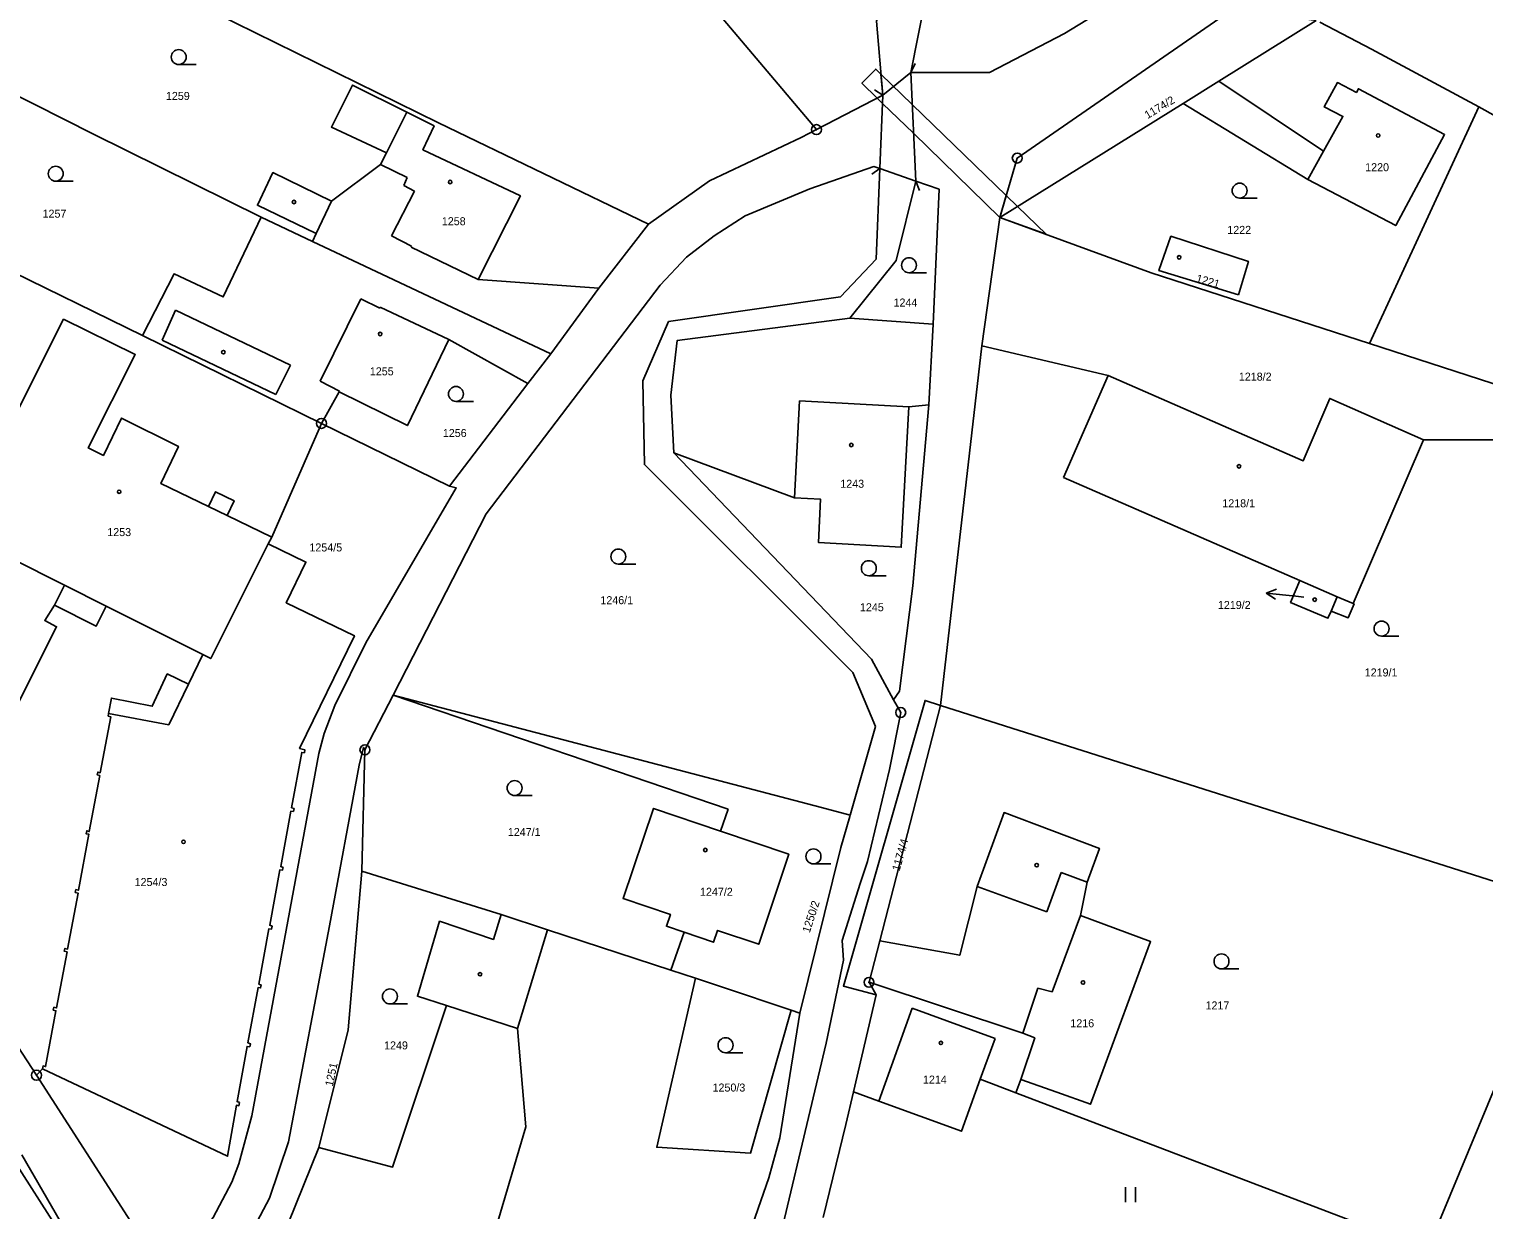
# Model space of a CAD drawing. Extents: x -587171 to -555306, y -1167727 to -1074732.
# Drawn here: x -559980.4 to -559834.5, y -1076843.9 to -1076725.4 of the extents above; entities that cross this region are included whole.
import ezdxf

# ---------------------------------------------------------------- set-up
doc = ezdxf.new("R2010")
doc.units = 0
for name, color, linetype in [('Hranice parcel', 7, 'Continuous'), ('Parcelní čísla', 7, 'Continuous'), ('Pop  PČ popisy', 7, 'Continuous'), ('Poz předměty', 7, 'Continuous'), ('Vnitřní kresba', 7, 'Continuous'), ('Věcná břemena k části', 7, 'Continuous'), ('Značky bodu BP', 7, 'Continuous'), ('Značky budov', 7, 'Continuous'), ('Značky kultur', 7, 'Continuous')]:
    doc.layers.add(name, color=color, linetype=linetype)

msp = doc.modelspace()

# ---------------------------------------------------------------- linework, layer by layer
at = {"layer": 'Hranice parcel'}
for p, q in [((-559861.1, -1076730.63), (-559851.34, -1076724.55)), ((-559892, -1076729.76), (-559891.5, -1076740.66)), ((-559864.67, -1076732.85), (-559861.1, -1076730.63)), ((-559894.79, -1076732.04), (-559901.45, -1076735.49)), ((-559895.09, -1076739.4), (-559894.79, -1076732.04)), ((-559883.05, -1076744.29), (-559864.67, -1076732.85)), ((-559845.98, -1076756.95), (-559835.03, -1076733.2)), ((-559828.11, -1076737.08), (-559835.03, -1076733.2)), ((-560001.56, -1076740.2), (-559969.04, -1076756.15)), ((-559889.14, -1076741.46), (-559891.5, -1076740.66)), ((-559889.75, -1076754.99), (-559889.14, -1076741.46)), ((-559951.99, -1076746.71), (-559957.13, -1076744.28)), ((-559918.29, -1076744.98), (-559923.28, -1076751.41)), ((-559883.05, -1076744.29), (-559884.86, -1076757.19)), ((-559928.09, -1076757.97), (-559951.99, -1076746.71)), ((-559923.28, -1076751.41), (-559928.09, -1076757.97)), ((-559889.75, -1076754.99), (-559898.09, -1076754.41)), ((-559890.17, -1076763.1), (-559889.75, -1076754.99)), ((-559969.04, -1076756.15), (-559951.09, -1076764.96)), ((-559830.5, -1076761.96), (-559845.98, -1076756.95)), ((-559928.09, -1076757.97), (-559930.38, -1076760.96)), ((-559884.86, -1076757.19), (-559889.01, -1076793.25)), ((-559884.86, -1076757.19), (-559872.19, -1076760.16)), ((-559930.38, -1076760.96), (-559938.25, -1076771.25)), ((-559872.19, -1076760.16), (-559876.67, -1076770.39)), ((-559956.07, -1076776.37), (-559951.09, -1076764.96)), ((-559951.09, -1076764.96), (-559938.25, -1076771.25)), ((-559847.63, -1076783.04), (-559840.58, -1076766.61)), ((-559840.58, -1076766.61), (-559823.35, -1076766.61)), ((-559876.67, -1076770.39), (-559852.96, -1076780.72)), ((-559956.42, -1076777.06), (-559956.07, -1076776.37)), ((-559943.91, -1076792.23), (-559946.73, -1076797.71)), ((-559910.3, -1076803.67), (-559943.91, -1076792.23)), ((-559889.01, -1076793.25), (-559895.1, -1076816.87)), ((-559825.87, -1076813.36), (-559889.01, -1076793.25)), ((-559946.73, -1076797.71), (-559947.03, -1076809.88)), ((-559911.09, -1076805.87), (-559910.3, -1076803.67)), ((-559947.03, -1076809.88), (-559933.08, -1076814.22)), ((-559840.17, -1076847.86), (-559825.87, -1076813.36)), ((-559933.08, -1076814.22), (-559928.42, -1076815.77)), ((-559928.42, -1076815.77), (-559916.07, -1076819.81)), ((-559916.07, -1076819.81), (-559914.72, -1076816.02)), ((-559895.1, -1076816.87), (-559896.18, -1076821.04)), ((-559916.07, -1076819.81), (-559913.57, -1076820.63)), ((-559896.18, -1076821.04), (-559895.46, -1076822.31)), ((-559895.46, -1076822.31), (-559897.72, -1076832.03)), ((-559903.99, -1076823.85), (-559903.12, -1076824.14)), ((-559979.67, -1076830.36), (-559979.07, -1076829.73)), ((-559881.44, -1076832.12), (-559880.97, -1076830.78)), ((-559840.17, -1076847.86), (-559881.44, -1076832.12)), ((-559951.35, -1076837.61), (-559960.01, -1076858.96))]:
    msp.add_line(p, q, dxfattribs=at)
for points in [[(-559958.09, -1076699.95), (-559954.36, -1076701.7), (-559913.91, -1076720.68), (-559901.45, -1076735.49)], [(-559894.79, -1076732.04), (-559895.44, -1076724.62), (-559892.05, -1076713.34), (-559886.72, -1076702.24)], [(-559885.03, -1076703.32), (-559887.56, -1076708.1), (-559889.85, -1076718.91), (-559892, -1076729.76)], [(-559892, -1076729.76), (-559884.1, -1076729.75), (-559876.58, -1076725.85), (-559869.98, -1076721.78), (-559855.77, -1076713.57), (-559855.15, -1076713.16)], [(-559918.29, -1076744.98), (-559939.37, -1076734.8), (-559961.79, -1076723.77), (-559967.51, -1076721.16)], [(-559851.34, -1076724.55), (-559859.71, -1076723.41), (-559881.31, -1076738.34), (-559883.05, -1076744.29)], [(-559835.03, -1076733.2), (-559845.8, -1076727.41), (-559850.96, -1076724.72)], [(-559957.13, -1076744.28), (-559973.96, -1076735.95), (-559994.8, -1076725.4)], [(-559864.67, -1076732.85), (-559852.18, -1076740.5), (-559843.36, -1076745.12), (-559838.45, -1076735.98), (-559847.1, -1076731.38), (-559847.3, -1076731.75), (-559849.21, -1076730.76), (-559850.53, -1076733.21), (-559848.65, -1076734.16), (-559850.6, -1076737.65), (-559861.1, -1076730.63)], [(-559923.28, -1076751.41), (-559935.36, -1076750.52), (-559931.14, -1076742.14), (-559940.92, -1076737.5), (-559939.79, -1076735.11), (-559942.52, -1076733.74), (-559947.97, -1076731.02), (-559950.09, -1076735.23), (-559944.57, -1076737.81), (-559945.16, -1076738.99), (-559950.08, -1076742.66), (-559955.96, -1076739.8), (-559957.51, -1076743.07), (-559951.62, -1076745.91), (-559951.99, -1076746.71)], [(-559901.45, -1076735.49), (-559902.97, -1076736.28), (-559912.17, -1076740.63), (-559918.29, -1076744.98)], [(-559895.09, -1076739.4), (-559895.7, -1076739.19), (-559902.1, -1076741.42), (-559908.6, -1076744.13), (-559911.72, -1076746.15), (-559914.48, -1076748.29), (-559917.14, -1076751.1), (-559934.56, -1076774.04), (-559943.91, -1076792.23)], [(-559898.06, -1076804.27), (-559895.52, -1076795.36), (-559897.79, -1076789.94), (-559918.71, -1076769.1), (-559918.87, -1076760.68), (-559916.28, -1076754.75), (-559899.04, -1076752.26), (-559895.45, -1076748.47), (-559895.09, -1076739.4)], [(-559891.5, -1076740.66), (-559893.46, -1076748.63), (-559898.09, -1076754.41)], [(-559957.13, -1076744.28), (-559960.94, -1076752.28), (-559965.87, -1076749.97), (-559969.04, -1076756.15)], [(-559845.98, -1076756.95), (-559867.87, -1076749.84), (-559883.05, -1076744.29)], [(-559859.11, -1076752.05), (-559858.13, -1076748.71), (-559865.9, -1076746.19), (-559867.1, -1076749.63), (-559859.11, -1076752.05)], [(-559956.07, -1076776.37), (-559960.56, -1076774.2), (-559959.85, -1076772.72), (-559961.71, -1076771.82), (-559962.42, -1076773.3), (-559967.2, -1076771), (-559965.43, -1076767.28), (-559971.14, -1076764.43), (-559972.96, -1076768.17), (-559974.48, -1076767.42), (-559969.76, -1076758.06), (-559976.96, -1076754.51), (-559987.65, -1076775.79), (-559976.87, -1076781.2), (-559977.88, -1076783.21)], [(-559898.09, -1076754.41), (-559915.43, -1076756.66), (-559916.07, -1076762.12), (-559915.74, -1076767.92)], [(-559951.09, -1076764.96), (-559949.31, -1076761.81), (-559942.47, -1076765.18), (-559938.33, -1076756.54), (-559930.38, -1076760.96)], [(-559840.58, -1076766.61), (-559849.97, -1076762.45), (-559852.63, -1076768.71), (-559872.19, -1076760.16)], [(-559915.74, -1076767.92), (-559903.66, -1076772.42), (-559901.05, -1076772.56), (-559901.25, -1076776.91), (-559892.95, -1076777.39), (-559892.18, -1076763.31), (-559890.17, -1076763.1)], [(-559893.71, -1076792.69), (-559893.13, -1076791.83), (-559891.78, -1076781.27), (-559890.17, -1076763.1)], [(-559915.74, -1076767.92), (-559895.94, -1076788.62), (-559893.71, -1076792.69)], [(-559938.25, -1076771.25), (-559937.57, -1076771.44), (-559946.65, -1076786.97), (-559949.75, -1076793.25), (-559950.81, -1076796.07), (-559951.35, -1076798.09), (-559958.07, -1076834.44), (-559959.38, -1076839.26), (-559960.09, -1076841.08), (-559961.95, -1076844.64), (-559962.87, -1076845.81), (-559964.08, -1076846.68), (-559965.52, -1076847.13), (-559967.49, -1076847.03), (-559968.86, -1076846.47), (-559969.95, -1076845.48), (-559979.67, -1076830.36)], [(-559979.07, -1076829.73), (-559960.51, -1076838.49), (-559959.62, -1076833.37), (-559959.37, -1076833.42), (-559959.32, -1076833.11), (-559959.55, -1076833.01), (-559958.55, -1076827.47), (-559958.29, -1076827.5), (-559958.22, -1076827.21), (-559958.46, -1076827.11), (-559957.45, -1076821.57), (-559957.19, -1076821.6), (-559957.13, -1076821.31), (-559957.37, -1076821.22), (-559956.36, -1076815.67), (-559956.1, -1076815.7), (-559956.03, -1076815.41), (-559956.27, -1076815.32), (-559955.27, -1076809.77), (-559955, -1076809.8), (-559954.94, -1076809.52), (-559955.18, -1076809.42), (-559954.17, -1076803.87), (-559953.91, -1076803.9), (-559953.84, -1076803.61), (-559954.09, -1076803.52), (-559953.07, -1076797.98), (-559952.8, -1076798.01), (-559952.75, -1076797.72), (-559953.28, -1076797.57), (-559947.79, -1076786.27), (-559954.62, -1076782.96), (-559952.65, -1076778.87), (-559956.42, -1076777.06)], [(-559962.98, -1076788.16), (-559962.19, -1076788.56), (-559956.42, -1076777.06)], [(-559847.63, -1076783.04), (-559847.53, -1076783.08), (-559848.14, -1076784.48), (-559849.84, -1076783.79), (-559850.16, -1076784.52), (-559853.91, -1076782.92), (-559852.96, -1076780.72)], [(-559852.96, -1076780.72), (-559849.22, -1076782.35), (-559847.63, -1076783.04)], [(-559989.66, -1076809.25), (-559977.66, -1076785.36), (-559978.85, -1076784.74), (-559977.88, -1076783.21)], [(-559977.88, -1076783.21), (-559973.69, -1076785.31), (-559972.68, -1076783.3), (-559962.98, -1076788.16)], [(-559962.98, -1076788.16), (-559964.41, -1076791.12), (-559966.55, -1076790.09), (-559968.06, -1076793.34), (-559972.16, -1076792.53), (-559972.45, -1076794.07), (-559972.48, -1076794.33), (-559972.22, -1076794.4), (-559973.28, -1076800.01), (-559973.53, -1076799.94), (-559973.58, -1076800.23), (-559973.32, -1076800.3), (-559974.38, -1076805.91), (-559974.63, -1076805.84), (-559974.69, -1076806.13), (-559974.42, -1076806.19), (-559975.46, -1076811.8), (-559975.72, -1076811.73), (-559975.79, -1076812.02), (-559975.5, -1076812.09), (-559976.56, -1076817.7), (-559976.82, -1076817.63), (-559976.88, -1076817.93), (-559976.61, -1076817.99), (-559977.66, -1076823.6), (-559977.92, -1076823.54), (-559977.99, -1076823.82), (-559977.72, -1076823.89), (-559978.76, -1076829.5), (-559979.01, -1076829.43), (-559979.07, -1076829.73)], [(-559943.91, -1076792.23), (-559900.95, -1076803.51), (-559898.06, -1076804.27)], [(-559893.71, -1076792.69), (-559893, -1076793.97), (-559894.13, -1076799.69), (-559896.32, -1076808.92), (-559897.08, -1076811.11), (-559898.86, -1076816.86), (-559898.74, -1076818.83), (-559900.49, -1076827.14), (-559906.6, -1076852.89), (-559908.24, -1076858.44), (-559911.74, -1076865.26), (-559915.45, -1076870.63), (-559919.41, -1076877.27), (-559922.9, -1076883.06), (-559924.6, -1076886.14), (-559925.8, -1076888.87), (-559926.41, -1076891.33), (-559926.98, -1076894.26), (-559927.14, -1076895.8), (-559927.07, -1076901.25), (-559927.09, -1076902.41), (-559927.45, -1076903.76), (-559927.26, -1076909.55), (-559926.75, -1076915.47)], [(-559895.46, -1076822.31), (-559898.75, -1076821.42), (-559890.56, -1076792.76), (-559889.01, -1076793.25)], [(-559946.73, -1076797.71), (-559946.89, -1076797.47), (-559947.31, -1076799.25), (-559950.3, -1076815.38), (-559954.4, -1076837.03), (-559956.29, -1076842.71), (-559959.37, -1076848.52), (-559960.75, -1076850.63), (-559962, -1076853.34), (-559962.43, -1076855.22), (-559960.01, -1076858.96)], [(-559974.06, -1076851.25), (-559985.47, -1076833.41), (-559985.58, -1076833.22), (-559989.34, -1076832.67), (-560002.27, -1076812.43), (-560004.14, -1076810.1), (-560006.38, -1076808.1), (-560006.59, -1076807.71), (-560006.43, -1076807.18), (-560004.56, -1076804.79), (-560020.92, -1076798.81)], [(-559914.72, -1076816.02), (-559916.5, -1076815.42), (-559916.1, -1076814.23), (-559920.84, -1076812.63), (-559917.79, -1076803.6), (-559911.09, -1076805.87)], [(-559903.12, -1076824.14), (-559898.99, -1076807.52), (-559898.1, -1076804.4), (-559898.06, -1076804.27)], [(-559880.97, -1076830.78), (-559877.34, -1076832.07), (-559873.97, -1076833.27), (-559873.2, -1076831.19), (-559867.94, -1076816.96), (-559874.96, -1076814.35), (-559874.31, -1076811), (-559873.08, -1076807.61), (-559882.64, -1076804.01), (-559885.35, -1076811.41), (-559887.08, -1076818.32), (-559895.1, -1076816.87)], [(-559914.72, -1076816.02), (-559911.76, -1076817.02), (-559911.36, -1076815.84), (-559907.23, -1076817.22), (-559904.23, -1076808.19), (-559911.09, -1076805.87)], [(-559979.67, -1076830.36), (-559991.31, -1076812.54), (-559989.66, -1076809.25)], [(-559947.03, -1076809.88), (-559948.43, -1076825.8), (-559951.35, -1076837.61)], [(-559933.08, -1076814.22), (-559933.85, -1076816.73), (-559939.25, -1076814.91), (-559941.47, -1076822.44), (-559938.56, -1076823.37), (-559943.96, -1076839.58), (-559951.35, -1076837.61)], [(-559944.37, -1076882.14), (-559930.58, -1076835.53), (-559931.44, -1076825.66), (-559928.42, -1076815.77)], [(-559903.99, -1076823.85), (-559908.06, -1076838.17), (-559917.46, -1076837.59), (-559913.57, -1076820.63)], [(-559913.57, -1076820.63), (-559910.97, -1076821.49), (-559903.99, -1076823.85)], [(-559880.97, -1076830.78), (-559879.56, -1076826.62), (-559880.77, -1076826.13), (-559896.18, -1076821.04)], [(-559929.99, -1076898.85), (-559930.15, -1076891.71), (-559929.66, -1076888.28), (-559926.11, -1076882.16), (-559919.8, -1076873.52), (-559917.9, -1076870.53), (-559913.28, -1076860.94), (-559906.24, -1076840.65), (-559905.14, -1076836.63), (-559903.12, -1076824.14)], [(-559897.72, -1076832.03), (-559895.19, -1076832.95), (-559886.91, -1076835.98), (-559885.02, -1076830.76), (-559881.44, -1076832.12)], [(-559897.72, -1076832.03), (-559898.51, -1076835.29), (-559900.77, -1076844.65)]]:
    msp.add_lwpolyline(points, dxfattribs=at)
at = {"layer": 'Pop  PČ popisy'}
for p, q in [((-559856.36, -1076781.99), (-559855.32, -1076781.59)), ((-559853.38, -1076782.3), (-559856.36, -1076781.99)), ((-559856.36, -1076781.99), (-559855.42, -1076782.59)), ((-559852.56, -1076782.39), (-559853.38, -1076782.3))]:
    msp.add_line(p, q, dxfattribs=at)
at = {"layer": 'Poz předměty'}
msp.add_line((-559952.18, -1076888.34), (-559981.15, -1076838.35), dxfattribs=at)
at = {"layer": 'Vnitřní kresba'}
for p, q in [((-559891.56, -1076728.86), (-559892, -1076729.76)), ((-559894.79, -1076732.04), (-559892, -1076729.76)), ((-559895.63, -1076731.5), (-559894.79, -1076732.04)), ((-559942.52, -1076733.74), (-559944.57, -1076737.81)), ((-559852.18, -1076740.5), (-559850.6, -1076737.65)), ((-559942.51, -1076740.29), (-559945.16, -1076738.99)), ((-559895.91, -1076739.97), (-559895.09, -1076739.4)), ((-559895.09, -1076739.4), (-559891.5, -1076740.66)), ((-559942.82, -1076741.09), (-559942.51, -1076740.29)), ((-559941.77, -1076741.65), (-559942.82, -1076741.09)), ((-559891.11, -1076741.58), (-559891.5, -1076740.66)), ((-559944.08, -1076746.14), (-559941.77, -1076741.65)), ((-559950.08, -1076742.66), (-559951.62, -1076745.91)), ((-559942.07, -1076747.18), (-559944.08, -1076746.14)), ((-559942.11, -1076747.27), (-559942.07, -1076747.18)), ((-559935.36, -1076750.52), (-559942.11, -1076747.27)), ((-559951.22, -1076760.71), (-559947.13, -1076752.48)), ((-559947.13, -1076752.48), (-559945.24, -1076753.41)), ((-559967.08, -1076756.61), (-559965.74, -1076753.59)), ((-559965.74, -1076753.59), (-559954.21, -1076759.11)), ((-559945.24, -1076753.41), (-559945.19, -1076753.29)), ((-559945.19, -1076753.29), (-559938.33, -1076756.54)), ((-559955.68, -1076762.06), (-559967.08, -1076756.61)), ((-559954.21, -1076759.11), (-559955.68, -1076762.06)), ((-559949.27, -1076761.72), (-559951.22, -1076760.71)), ((-559949.31, -1076761.81), (-559949.27, -1076761.72)), ((-559903.66, -1076772.42), (-559903.14, -1076762.69)), ((-559903.14, -1076762.69), (-559892.18, -1076763.31)), ((-559962.42, -1076773.3), (-559960.56, -1076774.2)), ((-559972.68, -1076783.3), (-559976.87, -1076781.2)), ((-559849.22, -1076782.35), (-559849.84, -1076783.79)), ((-559966.39, -1076795.22), (-559964.41, -1076791.12)), ((-559972.45, -1076794.07), (-559966.39, -1076795.22)), ((-559878.35, -1076813.96), (-559876.91, -1076810.02)), ((-559876.91, -1076810.02), (-559874.31, -1076811)), ((-559885.35, -1076811.41), (-559878.35, -1076813.96)), ((-559874.96, -1076814.35), (-559877.82, -1076821.99)), ((-559879.25, -1076821.64), (-559880.77, -1076826.13)), ((-559877.82, -1076821.99), (-559879.25, -1076821.64)), ((-559931.44, -1076825.66), (-559938.56, -1076823.37)), ((-559895.19, -1076832.95), (-559891.86, -1076823.62)), ((-559891.86, -1076823.62), (-559883.54, -1076826.66)), ((-559883.54, -1076826.66), (-559885.02, -1076830.76))]:
    msp.add_line(p, q, dxfattribs=at)
at = {"layer": 'Věcná břemena k části'}
for points in [[(-559895.35, -1076732.33), (-559894.79, -1076732.04), (-559894.98, -1076729.92), (-559895.5, -1076729.41), (-559896.89, -1076730.84)], [(-559883.05, -1076744.29), (-559882.41, -1076742.11), (-559891.85, -1076732.95), (-559894.98, -1076729.92), (-559894.79, -1076732.04), (-559895.35, -1076732.33), (-559894.82, -1076732.85), (-559891.72, -1076735.85)], [(-559883.05, -1076744.29), (-559881.29, -1076743.19), (-559882.41, -1076742.11)], [(-559878.41, -1076745.99), (-559881.29, -1076743.19), (-559883.05, -1076744.29)]]:
    msp.add_lwpolyline(points, close=True, dxfattribs=at)
at = {"layer": 'Značky bodu BP'}
for centre, radius in [((-559901.45, -1076735.49), 0.5), ((-559901.45, -1076735.49), 0.0303), ((-559881.31, -1076738.34), 0.5), ((-559881.31, -1076738.34), 0.0303), ((-559951.09, -1076764.96), 0.5), ((-559951.09, -1076764.96), 0.0303), ((-559893, -1076793.97), 0.5), ((-559893, -1076793.97), 0.0303), ((-559946.73, -1076797.71), 0.5), ((-559946.73, -1076797.71), 0.0303), ((-559896.18, -1076821.04), 0.5), ((-559896.18, -1076821.04), 0.0303), ((-559979.67, -1076830.36), 0.5), ((-559979.67, -1076830.36), 0.0303)]:
    msp.add_circle(centre, radius, dxfattribs=at)
at = {"layer": 'Značky budov'}
for centre in [(-559845.12, -1076736.08), (-559938.18, -1076740.75), (-559953.85, -1076742.75), (-559865.08, -1076748.3), (-559945.21, -1076755.99), (-559960.93, -1076757.82), (-559897.96, -1076767.13), (-559859.07, -1076769.27), (-559971.38, -1076771.82), (-559851.48, -1076782.64), (-559964.93, -1076806.94), (-559912.6, -1076807.77), (-559879.36, -1076809.28), (-559935.19, -1076820.23), (-559874.72, -1076821.06), (-559888.97, -1076827.12)]:
    msp.add_circle(centre, 0.175, dxfattribs=at)
at = {"layer": 'Značky kultur'}
for p, q in [((-559965.41, -1076728.96), (-559963.66, -1076728.96)), ((-559977.74, -1076740.66), (-559975.99, -1076740.66)), ((-559859.01, -1076742.36), (-559857.26, -1076742.36)), ((-559892.17, -1076749.84), (-559890.42, -1076749.84)), ((-559937.6, -1076762.76), (-559935.85, -1076762.76)), ((-559921.32, -1076779.07), (-559919.57, -1076779.07)), ((-559896.2, -1076780.24), (-559894.45, -1076780.24)), ((-559844.78, -1076786.3), (-559843.03, -1076786.3)), ((-559931.72, -1076802.3), (-559929.97, -1076802.3)), ((-559901.75, -1076809.16), (-559900, -1076809.16)), ((-559860.83, -1076819.69), (-559859.08, -1076819.69)), ((-559944.22, -1076823.21), (-559942.47, -1076823.21)), ((-559910.57, -1076828.1), (-559908.82, -1076828.1)), ((-559870.47, -1076843.1), (-559870.47, -1076841.6)), ((-559869.47, -1076843.1), (-559869.47, -1076841.6))]:
    msp.add_line(p, q, dxfattribs=at)
for centre in [(-559965.41, -1076728.21), (-559977.74, -1076739.91), (-559859.01, -1076741.61), (-559892.17, -1076749.09), (-559937.6, -1076762.01), (-559921.32, -1076778.32), (-559896.2, -1076779.49), (-559844.78, -1076785.55), (-559931.72, -1076801.55), (-559901.75, -1076808.41), (-559860.83, -1076818.94), (-559944.22, -1076822.46), (-559910.57, -1076827.35)]:
    msp.add_circle(centre, 0.75, dxfattribs=at)

# ---------------------------------------------------------------- texts
at = {"layer": 'Parcelní čísla'}
for s, p in [('1259', (-559966.69, -1076732.51)), ('1220', (-559846.42, -1076739.66)), ('1257', (-559979.06, -1076744.32)), ('1258', (-559939.02, -1076745.08)), ('1222', (-559860.25, -1076745.95)), ('1244', (-559893.72, -1076753.24)), ('1255', (-559946.24, -1076760.14)), ('1218/2', (-559859.09, -1076760.67)), ('1256', (-559938.92, -1076766.33)), ('1243', (-559899.06, -1076771.42)), ('1218/1', (-559860.75, -1076773.38)), ('1253', (-559972.57, -1076776.27)), ('1254/5', (-559952.3, -1076777.81)), ('1246/1', (-559923.12, -1076783.1)), ('1245', (-559897.09, -1076783.81)), ('1219/2', (-559861.19, -1076783.58)), ('1219/1', (-559846.47, -1076790.35)), ('1247/1', (-559932.4, -1076806.36)), ('1254/3', (-559969.83, -1076811.38)), ('1247/2', (-559913.13, -1076812.36)), ('1217', (-559862.43, -1076823.76)), ('1216', (-559875.99, -1076825.55)), ('1249', (-559944.81, -1076827.77)), ('1250/3', (-559911.87, -1076832)), ('1214', (-559890.77, -1076831.2))]:
    msp.add_text(s, height=0.803, dxfattribs=at).set_placement(p)
for s, rotation, p in [('1174/2', 31, (-559868.25, -1076734.44)), ('1221', 344, (-559863.44, -1076750.75)), ('1174/4', 74, (-559893.12, -1076809.93)), ('1250/2', 72, (-559902.13, -1076816.13)), ('1251', 78, (-559949.96, -1076831.53))]:
    msp.add_text(s, height=0.803, rotation=rotation, dxfattribs=at).set_placement(p)

doc.saveas('drawing.dxf')
